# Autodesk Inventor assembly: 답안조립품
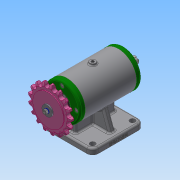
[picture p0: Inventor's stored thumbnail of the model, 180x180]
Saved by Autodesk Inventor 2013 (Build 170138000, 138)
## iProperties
Created: 2019-06
Part Number: 답안조립품
Document SubType Name: Assembly
Designer: Administrator
Author: Administrator
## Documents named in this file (11)
- C:\Users\Administrator\Desktop\490604V1022\답안조립품.iam
- C:\Users\Administrator\Desktop\490604V1022\본체.ipt
- C:\Users\Administrator\Desktop\490604V1022\베어링 6203.ipt
- C:\Users\Administrator\Desktop\490604V1022\볼트 M4.ipt
- C:\Users\Administrator\Desktop\490604V1022\스프로킷.ipt
- C:\Users\Administrator\Desktop\490604V1022\스프링와셔.ipt
- C:\Users\Administrator\Desktop\490604V1022\오일 실 17 30 5.ipt
- C:\Users\Administrator\Desktop\490604V1022\축.ipt
- C:\Users\Administrator\Desktop\490604V1022\커버.ipt
- C:\Users\Administrator\Desktop\490604V1022\키 4x4x12.ipt
- C:\Users\Administrator\Desktop\490604V1022\평와셔.ipt
